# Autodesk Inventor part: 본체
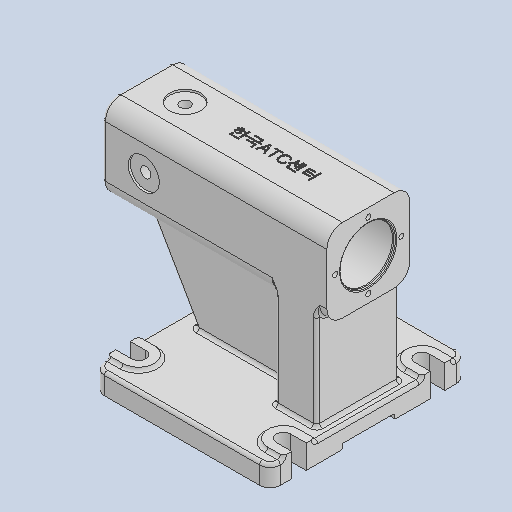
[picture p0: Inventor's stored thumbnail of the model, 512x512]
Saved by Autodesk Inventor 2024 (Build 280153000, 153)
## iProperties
Created: 2024-08
Part Number: 본체
Material: 일반
Document SubType Name: Modeling
Designer: user
Density: 1 g/cm^3
Appearance: 기본값
Author: jhkim
Sending System: Autodesk Inventor 2025
Preprocessor: ST-DEVELOPER v20
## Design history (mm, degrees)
feature "솔리드1"
node "솔리드2"
